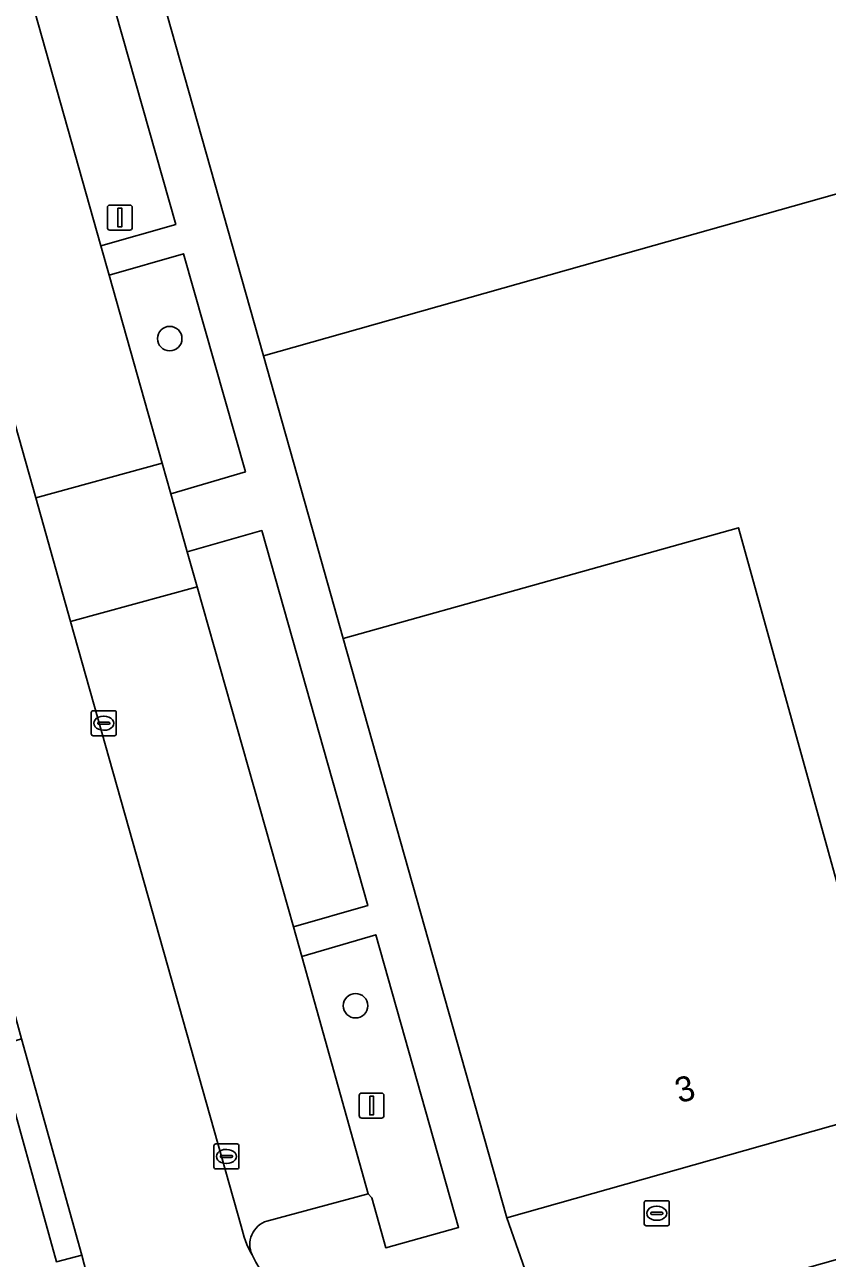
# Model space of a CAD drawing. Extents: x 159680 to 160786, y 387323 to 388340.
# Drawn here: x 159828.45 to 159860.51, y 387960.21 to 388009.45 of the extents above; entities that cross this region are included whole.
import ezdxf

# ---------------------------------------------------------------- set-up
doc = ezdxf.new("R2010")
doc.units = 0
for name, color, linetype in [('IMGEO_Boom', 7, 'Continuous'), ('IMGEO_Brandkraan', 7, 'Continuous'), ('IMGEO_Groenvoorziening', 7, 'Continuous'), ('IMGEO_Kolk', 7, 'Continuous'), ('IMGEO_Lichtmast', 7, 'Continuous'), ('IMGEO_Pand', 7, 'Continuous'), ('IMGEO_Pand_nummerreeks', 7, 'Continuous'), ('IMGEO_Parkeervlak_open', 7, 'Continuous'), ('IMGEO_Rijbaan_lokaal_gesloten', 7, 'Continuous'), ('IMGEO_Voetpad_gesloten', 7, 'Continuous'), ('IMGEO_Voetpad_open', 7, 'Continuous')]:
    doc.layers.add(name, color=color, linetype=linetype)

msp = doc.modelspace()

# ---------------------------------------------------------------- linework, layer by layer
at = {"layer": 'IMGEO_Boom'}
for centre in [(159834.245, 387996.922), (159841.664, 387970.294)]:
    msp.add_circle(centre, 0.489, dxfattribs=at)
at = {"layer": 'IMGEO_Brandkraan'}
for p, q in [((159853.193, 387961.584), (159853.193, 387962.436)), ((159853.268, 387962.51), (159854.12, 387962.51)), ((159853.681, 387962.29), (159853.706, 387962.29)), ((159854.194, 387962.436), (159854.194, 387961.584)), ((159853.452, 387962.004), (159853.452, 387962.016)), ((159853.89, 387961.967), (159853.492, 387961.967)), ((159853.495, 387962.053), (159853.893, 387962.053)), ((159853.704, 387961.73), (159853.679, 387961.73)), ((159853.936, 387962.016), (159853.936, 387962.004)), ((159854.12, 387961.51), (159853.268, 387961.51))]:
    msp.add_line(p, q, dxfattribs=at)
for points in [[(159853.193, 387961.584), (159853.193, 387962.436)], [(159853.268, 387962.51), (159854.12, 387962.51)], [(159854.194, 387962.436), (159854.194, 387961.584)], [(159854.12, 387961.51), (159853.268, 387961.51)]]:
    msp.add_lwpolyline(points, dxfattribs=at)
for centre, radius, start, end in [((159853.27, 387962.434), 0.0765, 91.552, 178.448), ((159853.27, 387962.434), 0.0765, 91.552, 178.448), ((159854.118, 387962.434), 0.0765, 1.552, 88.448), ((159854.118, 387962.434), 0.0765, 1.552, 88.448), ((159853.492, 387962.013), 0.0403, 85.8775, 175.7526), ((159853.489, 387962.003), 0.0366, 178.938, 274.7102), ((159853.893, 387962.01), 0.043, 264.8664, 352.4533), ((159853.897, 387962.015), 0.0386, 1.7309, 96.639), ((159853.27, 387961.586), 0.0765, 181.552, 268.448), ((159853.27, 387961.586), 0.0765, 181.552, 268.448), ((159854.118, 387961.586), 0.0765, 271.552, 358.448), ((159854.118, 387961.586), 0.0765, 271.552, 358.448)]:
    msp.add_arc(centre, radius, start, end, dxfattribs=at)
for centre, major_axis, ratio, start_param, end_param in [((159853.68, 387962.01), (-0.387, 0.002), 0.722429, 4.712389, 7.853982), ((159853.705, 387962.01), (-0.39, 0.002), 0.717154, 1.570796, 4.712389)]:
    msp.add_ellipse(centre, major_axis=major_axis, ratio=ratio, start_param=start_param, end_param=end_param, dxfattribs=at)
at = {"layer": 'IMGEO_Groenvoorziening'}
for points in [[(159831.544, 388011.861), (159828.571, 388011.012), (159831.491, 388000.626), (159834.483, 388001.477)], [(159834.797, 388000.307), (159831.828, 387999.454), (159833.944, 387991.957), (159834.291, 387990.729), (159837.266, 387991.604)], [(159837.916, 387989.261), (159834.943, 387988.417), (159835.34, 387987.013), (159839.182, 387973.441), (159842.159, 387974.291)], [(159839.515, 387972.265), (159842.167, 387962.792), (159842.321, 387962.624), (159842.869, 387960.636), (159845.78, 387961.446), (159842.473, 387973.13)]]:
    msp.add_lwpolyline(points, close=True, dxfattribs=at)
at = {"layer": 'IMGEO_Kolk'}
for p, q in [((159831.109, 387981.144), (159831.109, 387981.996)), ((159831.184, 387982.07), (159832.036, 387982.07)), ((159832.11, 387981.996), (159832.11, 387981.144)), ((159831.368, 387981.564), (159831.368, 387981.576)), ((159831.806, 387981.527), (159831.408, 387981.527)), ((159831.411, 387981.613), (159831.809, 387981.613)), ((159831.597, 387981.85), (159831.622, 387981.85)), ((159831.852, 387981.576), (159831.852, 387981.564)), ((159832.036, 387981.07), (159831.184, 387981.07)), ((159831.62, 387981.29), (159831.595, 387981.29)), ((159836.007, 387963.853), (159836.007, 387964.705)), ((159836.082, 387964.779), (159836.934, 387964.779)), ((159837.008, 387964.705), (159837.008, 387963.853)), ((159836.266, 387964.273), (159836.266, 387964.285)), ((159836.704, 387964.236), (159836.306, 387964.236)), ((159836.309, 387964.322), (159836.707, 387964.322)), ((159836.495, 387964.559), (159836.52, 387964.559)), ((159836.75, 387964.285), (159836.75, 387964.273)), ((159836.934, 387963.779), (159836.082, 387963.779)), ((159836.518, 387963.999), (159836.493, 387963.999))]:
    msp.add_line(p, q, dxfattribs=at)
for points in [[(159831.109, 387981.144), (159831.109, 387981.996)], [(159831.184, 387982.07), (159832.036, 387982.07)], [(159832.11, 387981.996), (159832.11, 387981.144)], [(159832.036, 387981.07), (159831.184, 387981.07)], [(159836.007, 387963.853), (159836.007, 387964.705)], [(159836.082, 387964.779), (159836.934, 387964.779)], [(159837.008, 387964.705), (159837.008, 387963.853)], [(159836.934, 387963.779), (159836.082, 387963.779)]]:
    msp.add_lwpolyline(points, dxfattribs=at)
for centre, radius, start, end in [((159831.186, 387981.994), 0.0765, 91.552, 178.448), ((159831.186, 387981.994), 0.0765, 91.552, 178.448), ((159832.034, 387981.994), 0.0765, 1.552, 88.448), ((159832.034, 387981.994), 0.0765, 1.552, 88.448), ((159831.408, 387981.573), 0.0403, 85.8775, 175.7526), ((159831.405, 387981.563), 0.0366, 178.938, 274.7102), ((159831.809, 387981.57), 0.043, 264.8664, 352.4533), ((159831.813, 387981.575), 0.0386, 1.7309, 96.639), ((159831.186, 387981.146), 0.0765, 181.552, 268.448), ((159831.186, 387981.146), 0.0765, 181.552, 268.448), ((159832.034, 387981.146), 0.0765, 271.552, 358.448), ((159832.034, 387981.146), 0.0765, 271.552, 358.448), ((159836.084, 387964.703), 0.0765, 91.552, 178.448), ((159836.084, 387964.703), 0.0765, 91.552, 178.448), ((159836.932, 387964.703), 0.0765, 1.552, 88.448), ((159836.932, 387964.703), 0.0765, 1.552, 88.448), ((159836.306, 387964.282), 0.0403, 85.8775, 175.7526), ((159836.303, 387964.272), 0.0366, 178.938, 274.7102), ((159836.707, 387964.279), 0.043, 264.8664, 352.4533), ((159836.711, 387964.284), 0.0386, 1.7309, 96.639), ((159836.084, 387963.855), 0.0765, 181.552, 268.448), ((159836.084, 387963.855), 0.0765, 181.552, 268.448), ((159836.932, 387963.855), 0.0765, 271.552, 358.448), ((159836.932, 387963.855), 0.0765, 271.552, 358.448)]:
    msp.add_arc(centre, radius, start, end, dxfattribs=at)
for centre, major_axis, ratio, start_param, end_param in [((159831.596, 387981.57), (-0.387, 0.002), 0.722429, 4.712389, 7.853982), ((159831.621, 387981.57), (-0.39, 0.002), 0.717154, 1.570796, 4.712389), ((159836.494, 387964.279), (-0.387, 0.002), 0.722429, 4.712389, 7.853982), ((159836.519, 387964.279), (-0.39, 0.002), 0.717154, 1.570796, 4.712389)]:
    msp.add_ellipse(centre, major_axis=major_axis, ratio=ratio, start_param=start_param, end_param=end_param, dxfattribs=at)
at = {"layer": 'IMGEO_Lichtmast'}
for p, q in [((159831.758, 388001.355), (159831.758, 388002.155)), ((159831.758, 388002.155), (159831.758, 388001.355)), ((159831.858, 388002.255), (159832.648, 388002.255)), ((159832.648, 388002.255), (159831.858, 388002.255)), ((159832.748, 388002.155), (159832.748, 388001.355)), ((159832.748, 388001.355), (159832.748, 388002.155)), ((159832.648, 388001.255), (159831.858, 388001.255)), ((159831.858, 388001.255), (159832.648, 388001.255)), ((159841.811, 387965.91), (159841.811, 387966.71)), ((159841.811, 387966.71), (159841.811, 387965.91)), ((159841.911, 387966.81), (159842.701, 387966.81)), ((159842.701, 387966.81), (159841.911, 387966.81)), ((159842.801, 387966.71), (159842.801, 387965.91)), ((159842.801, 387965.91), (159842.801, 387966.71)), ((159842.701, 387965.81), (159841.911, 387965.81)), ((159841.911, 387965.81), (159842.701, 387965.81))]:
    msp.add_line(p, q, dxfattribs=at)
for points in [[(159832.178, 388002.13), (159832.328, 388002.13), (159832.328, 388001.38), (159832.178, 388001.38), (159832.178, 388002.13)], [(159842.231, 387966.685), (159842.381, 387966.685), (159842.381, 387965.935), (159842.231, 387965.935), (159842.231, 387966.685)]]:
    msp.add_lwpolyline(points, dxfattribs=at)
for centre, start, end in [((159831.858, 388002.155), 90, 180), ((159831.858, 388002.155), 90, 180), ((159832.648, 388002.155), 0, 90), ((159832.648, 388002.155), 360, 90), ((159831.858, 388001.355), 180, 270), ((159831.858, 388001.355), 180, 270), ((159832.648, 388001.355), 270, 0), ((159832.648, 388001.355), 270, 0), ((159841.911, 387966.71), 90, 180), ((159841.911, 387966.71), 90, 180), ((159842.701, 387966.71), 0, 90), ((159842.701, 387966.71), 360, 90), ((159841.911, 387965.91), 180, 270), ((159841.911, 387965.91), 180, 270), ((159842.701, 387965.91), 270, 0), ((159842.701, 387965.91), 270, 0)]:
    msp.add_arc(centre, 0.1, start, end, dxfattribs=at)
at = {"layer": 'IMGEO_Pand'}
for points in [[(159836.727, 388031.661), (159837.686, 388028.235), (159829.597, 388025.911), (159836.928, 388000), (159837.992, 387996.231), (159851.316, 388000), (159869.229, 388005.056), (159869.487, 388004.143), (159882.299, 388007.76), (159877.892, 388024.247), (159874.489, 388023.234), (159871.155, 388035.219), (159868.062, 388036.545), (159864.143, 388035.468), (159860.548, 388034.481), (159860.469, 388034.822), (159859.87, 388035.171), (159859.769, 388035.23), (159853.295, 388033.388), (159852.93, 388032.688), (159853.022, 388032.345), (159848.853, 388031.171), (159848.627, 388031.984), (159847.843, 388034.798)], [(159841.177, 387984.948), (159856.965, 387989.373), (159863.381, 387966.257), (159879.363, 387970.77), (159870.657, 388000), (159869.487, 388004.143), (159869.229, 388005.056), (159851.316, 388000), (159837.992, 387996.231), (159839.921, 387989.398)], [(159845.868, 387968.327), (159847.702, 387961.83), (159863.381, 387966.257), (159856.965, 387989.373), (159841.177, 387984.948), (159842.331, 387980.857)]]:
    msp.add_lwpolyline(points, close=True, dxfattribs=at)
at = {"layer": 'IMGEO_Parkeervlak_open'}
msp.add_lwpolyline([(159825.088, 388023.358), (159820.027, 388021.979), (159828.892, 387990.568), (159833.944, 387991.957), (159831.828, 387999.454), (159831.491, 388000.626), (159828.571, 388011.012), (159828.234, 388012.174)], close=True, dxfattribs=at)
for points in [[(159839.182, 387973.441), (159835.34, 387987.013), (159830.287, 387985.625), (159837.095, 387961.501)], [(159838.122, 387961.701), (159842.167, 387962.792), (159839.515, 387972.265), (159839.182, 387973.441)]]:
    msp.add_lwpolyline(points, dxfattribs=at)
for centre, radius, start, end in [((159838.436, 387960.759), 0.993, 108.4083, 204.5017), ((159841.223, 387962.404), 4.226, 192.3454, 209.1362)]:
    msp.add_arc(centre, radius, start, end, dxfattribs=at)
at = {"layer": 'IMGEO_Rijbaan_lokaal_gesloten'}
for points in [[(159812.513, 388025.241), (159818.635, 388003.499), (159820.042, 387998.504), (159826.424, 387975.841), (159826.458, 387975.72), (159826.587, 387975.306), (159828.331, 387968.967), (159830.73, 387960.333), (159830.914, 387959.622), (159831.088, 387958.977), (159835.97, 387941.843), (159836.852, 387938.769), (159837.264, 387937.298), (159843.618, 387914.929), (159844.918, 387910.333), (159845.351, 387910.462), (159851.063, 387912.019), (159849.77, 387916.603), (159845.974, 387930.104), (159843.795, 387937.765), (159843.73, 387937.996), (159842.932, 387940.627)], [(159837.095, 387961.501), (159830.287, 387985.625), (159828.892, 387990.568), (159820.027, 388021.979)]]:
    msp.add_lwpolyline(points, dxfattribs=at)
for centre, radius, start, end in [((159841.223, 387962.404), 4.226, 192.3454, 209.1362), ((159844.78, 387964.043), 8.136, 207.0183, 279.8887)]:
    msp.add_arc(centre, radius, start, end, dxfattribs=at)
at = {"layer": 'IMGEO_Voetpad_gesloten'}
msp.add_lwpolyline([(159828.331, 387968.967), (159827.327, 387968.664), (159829.719, 387960.075), (159830.73, 387960.333)], close=True, dxfattribs=at)
at = {"layer": 'IMGEO_Voetpad_open'}
for points in [[(159847.702, 387961.83), (159845.868, 387968.327), (159842.331, 387980.857), (159841.177, 387984.948), (159839.921, 387989.398), (159837.992, 387996.231), (159836.928, 388000), (159829.597, 388025.911)], [(159831.544, 388011.861), (159834.483, 388001.477), (159831.491, 388000.626), (159831.828, 387999.454), (159834.797, 388000.307), (159837.266, 387991.604), (159834.291, 387990.729), (159834.943, 387988.417), (159837.916, 387989.261), (159842.159, 387974.291), (159839.182, 387973.441), (159839.515, 387972.265), (159842.473, 387973.13), (159845.78, 387961.446), (159842.869, 387960.636), (159842.321, 387962.624), (159842.167, 387962.792), (159838.122, 387961.701)], [(159975.19, 387997.872), (159966.45, 387995.384), (159966.303, 387995.342), (159957.118, 387992.727), (159919.517, 387982.109), (159918.971, 387981.955), (159912.006, 387979.988), (159891.972, 387974.331), (159879.363, 387970.77), (159863.381, 387966.257), (159847.702, 387961.83), (159849.42, 387956.928), (159867.201, 387961.954), (159885.981, 387967.286), (159904.721, 387972.567), (159921.263, 387977.213), (159939.339, 387982.319), (159960.046, 387988.14), (159976.848, 387992.866)], [(159830.914, 387959.622), (159830.73, 387960.333), (159829.719, 387960.075), (159827.327, 387968.664), (159825.349, 387966.806), (159827.001, 387960.983), (159827.812, 387958.075)], [(159846.177, 387956.028), (159846.182, 387956.029), (159849.42, 387956.928), (159847.702, 387961.83)]]:
    msp.add_lwpolyline(points, dxfattribs=at)
msp.add_lwpolyline([(159834.291, 387990.729), (159833.944, 387991.957), (159828.892, 387990.568), (159830.287, 387985.625), (159835.34, 387987.013), (159834.943, 387988.417)], close=True, dxfattribs=at)
for centre, radius, start, end in [((159838.436, 387960.759), 0.993, 108.4083, 204.5017), ((159844.78, 387964.043), 8.136, 207.0183, 279.8887)]:
    msp.add_arc(centre, radius, start, end, dxfattribs=at)

# ---------------------------------------------------------------- texts
at = {"layer": 'IMGEO_Pand_nummerreeks'}
msp.add_text('3', height=1, rotation=15.7705, dxfattribs=at).set_placement((159854.591, 387966.394))

doc.saveas('drawing.dxf')
